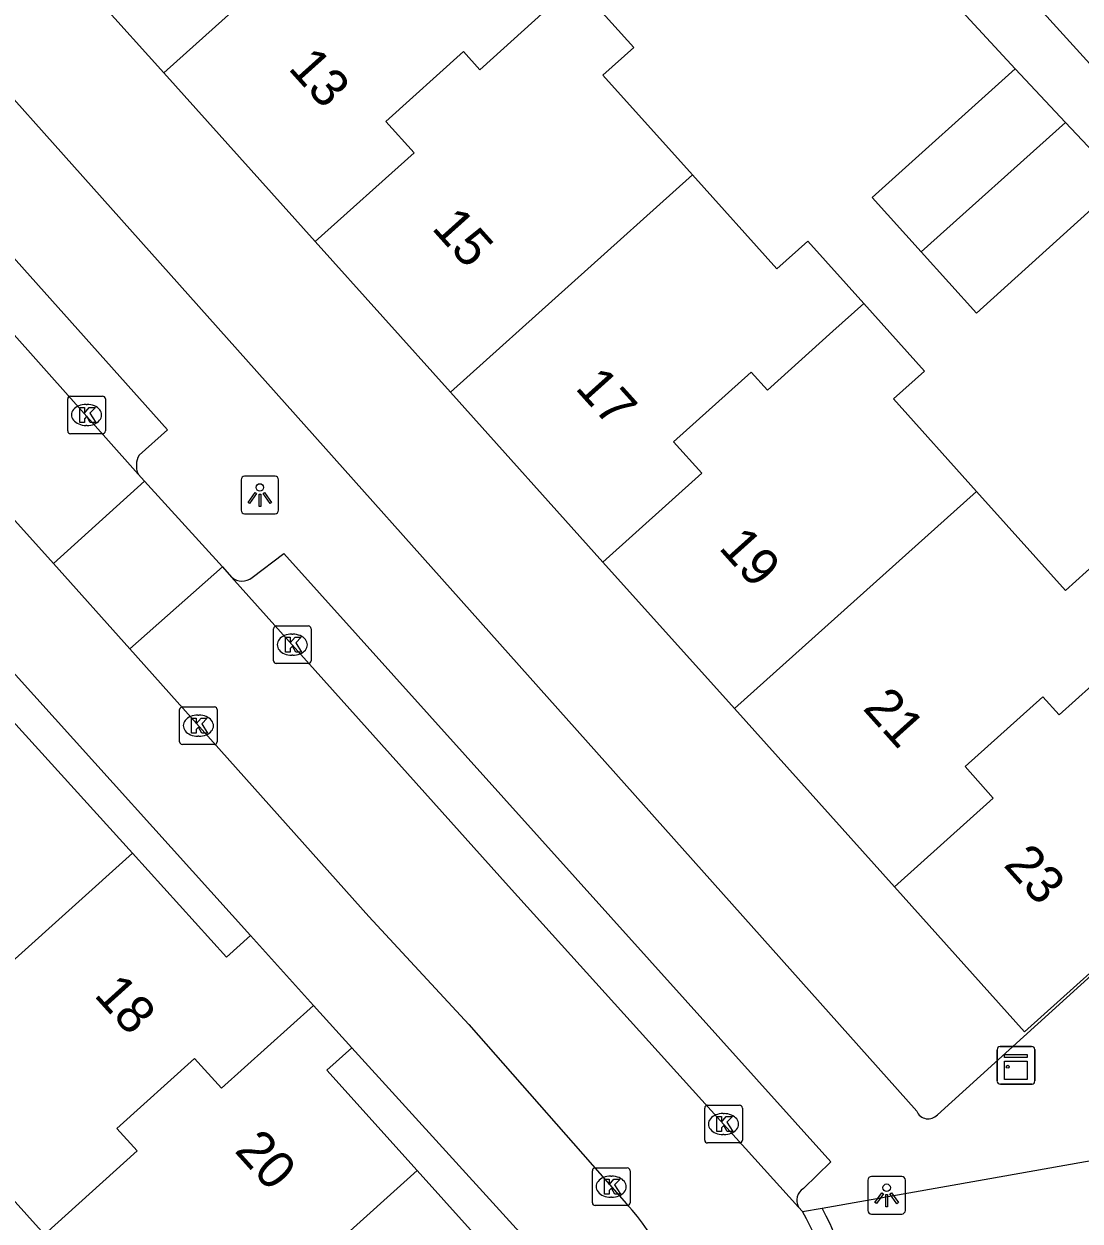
# Model space of a CAD drawing. Extents: x 162347 to 162868, y 381221 to 381813.
# Drawn here: x 162658.91 to 162687, y 381443.7 to 381475.54 of the extents above; entities that cross this region are included whole.
import ezdxf

# ---------------------------------------------------------------- set-up
doc = ezdxf.new("R2010")
doc.units = 0
for name, color, linetype in [('IMGEO_Kast', 7, 'Continuous'), ('IMGEO_Kolk', 7, 'Continuous'), ('IMGEO_Lichtpunt', 7, 'Continuous'), ('IMGEO_Pand', 7, 'Continuous'), ('IMGEO_Pand_nummerreeks', 7, 'Continuous'), ('IMGEO_Rijbaan_lokaal_gesloten', 7, 'Continuous'), ('IMGEO_Rijbaan_lokaal_open', 7, 'Continuous'), ('IMGEO_Voetpad_open', 7, 'Continuous')]:
    doc.layers.add(name, color=color, linetype=linetype)

msp = doc.modelspace()

# ---------------------------------------------------------------- linework, layer by layer
at = {"layer": 'IMGEO_Kast'}
for p, q in [((162684.796, 381447.418), (162684.796, 381448.259)), ((162684.796, 381448.259), (162684.796, 381447.418)), ((162684.871, 381448.343), (162685.712, 381448.343)), ((162685.712, 381448.343), (162684.871, 381448.343)), ((162685.796, 381448.268), (162685.796, 381447.427)), ((162685.796, 381447.427), (162685.796, 381448.268)), ((162685.721, 381447.343), (162684.88, 381447.343)), ((162684.88, 381447.343), (162685.721, 381447.343))]:
    msp.add_line(p, q, dxfattribs=at)
for points in [[(162684.991, 381448.133), (162685.591, 381448.133), (162685.591, 381448.048), (162684.991, 381448.048), (162684.991, 381448.133)], [(162684.991, 381447.958), (162685.591, 381447.958), (162685.591, 381447.469), (162684.991, 381447.469), (162684.991, 381447.958)]]:
    msp.add_lwpolyline(points, dxfattribs=at)
msp.add_circle((162685.075, 381447.807), 0.0377, dxfattribs=at)
for centre, start, end in [((162684.874, 381448.265), 92.4484, 184.2845), ((162684.874, 381448.265), 92.4484, 184.2845), ((162685.718, 381448.265), 2.4484, 94.2845), ((162685.718, 381448.265), 2.4484, 94.2845), ((162684.874, 381447.421), 182.4484, 274.2845), ((162684.874, 381447.421), 182.4484, 274.2845), ((162685.718, 381447.421), 272.4484, 4.2845), ((162685.718, 381447.421), 272.4484, 4.2845)]:
    msp.add_arc(centre, 0.0779, start, end, dxfattribs=at)
at = {"layer": 'IMGEO_Kolk'}
for p, q in [((162660.078, 381464.713), (162660.078, 381465.565)), ((162660.153, 381465.639), (162661.005, 381465.639)), ((162660.566, 381465.419), (162660.591, 381465.419)), ((162661.079, 381465.565), (162661.079, 381464.713)), ((162660.589, 381464.859), (162660.564, 381464.859)), ((162661.005, 381464.639), (162660.153, 381464.639)), ((162665.55, 381458.602), (162665.55, 381459.454)), ((162665.625, 381459.528), (162666.477, 381459.528)), ((162666.038, 381459.308), (162666.063, 381459.308)), ((162666.551, 381459.454), (162666.551, 381458.602)), ((162666.061, 381458.748), (162666.036, 381458.748)), ((162666.477, 381458.528), (162665.625, 381458.528)), ((162663.127, 381457.376), (162663.979, 381457.376)), ((162663.052, 381456.45), (162663.052, 381457.302)), ((162663.54, 381457.156), (162663.565, 381457.156)), ((162664.053, 381457.302), (162664.053, 381456.45)), ((162663.563, 381456.596), (162663.538, 381456.596)), ((162663.979, 381456.376), (162663.127, 381456.376)), ((162677.018, 381445.855), (162677.018, 381446.707)), ((162677.093, 381446.781), (162677.945, 381446.781)), ((162677.506, 381446.561), (162677.531, 381446.561)), ((162678.019, 381446.707), (162678.019, 381445.855)), ((162677.529, 381446.001), (162677.504, 381446.001)), ((162677.945, 381445.781), (162677.093, 381445.781)), ((162674.031, 381444.19), (162674.031, 381445.042)), ((162674.106, 381445.116), (162674.958, 381445.116)), ((162675.032, 381445.042), (162675.032, 381444.19)), ((162674.519, 381444.896), (162674.544, 381444.896)), ((162674.542, 381444.336), (162674.517, 381444.336)), ((162674.958, 381444.116), (162674.106, 381444.116))]:
    msp.add_line(p, q, dxfattribs=at)
for points in [[(162660.078, 381464.713), (162660.078, 381465.565)], [(162660.153, 381465.639), (162661.005, 381465.639)], [(162660.399, 381465.339), (162660.522, 381465.339), (162660.522, 381465.188), (162660.652, 381465.339), (162660.816, 381465.339), (162660.67, 381465.188), (162660.823, 381464.939), (162660.671, 381464.939), (162660.586, 381465.103), (162660.522, 381465.036), (162660.522, 381464.939), (162660.399, 381464.939), (162660.399, 381465.339)], [(162661.079, 381465.565), (162661.079, 381464.713)], [(162661.005, 381464.639), (162660.153, 381464.639)], [(162665.55, 381458.602), (162665.55, 381459.454)], [(162665.625, 381459.528), (162666.477, 381459.528)], [(162666.551, 381459.454), (162666.551, 381458.602)], [(162665.871, 381459.228), (162665.994, 381459.228), (162665.994, 381459.077), (162666.124, 381459.228), (162666.288, 381459.228), (162666.142, 381459.077), (162666.295, 381458.828), (162666.143, 381458.828), (162666.058, 381458.992), (162665.994, 381458.925), (162665.994, 381458.828), (162665.871, 381458.828), (162665.871, 381459.228)], [(162666.477, 381458.528), (162665.625, 381458.528)], [(162663.127, 381457.376), (162663.979, 381457.376)], [(162663.052, 381456.45), (162663.052, 381457.302)], [(162663.373, 381457.076), (162663.496, 381457.076), (162663.496, 381456.925), (162663.626, 381457.076), (162663.79, 381457.076), (162663.644, 381456.925), (162663.797, 381456.676), (162663.645, 381456.676), (162663.56, 381456.84), (162663.496, 381456.773), (162663.496, 381456.676), (162663.373, 381456.676), (162663.373, 381457.076)], [(162664.053, 381457.302), (162664.053, 381456.45)], [(162663.979, 381456.376), (162663.127, 381456.376)], [(162677.018, 381445.855), (162677.018, 381446.707)], [(162677.093, 381446.781), (162677.945, 381446.781)], [(162678.019, 381446.707), (162678.019, 381445.855)], [(162677.339, 381446.481), (162677.462, 381446.481), (162677.462, 381446.33), (162677.592, 381446.481), (162677.756, 381446.481), (162677.61, 381446.33), (162677.763, 381446.081), (162677.611, 381446.081), (162677.526, 381446.245), (162677.462, 381446.178), (162677.462, 381446.081), (162677.339, 381446.081), (162677.339, 381446.481)], [(162677.945, 381445.781), (162677.093, 381445.781)], [(162674.031, 381444.19), (162674.031, 381445.042)], [(162674.106, 381445.116), (162674.958, 381445.116)], [(162675.032, 381445.042), (162675.032, 381444.19)], [(162674.352, 381444.816), (162674.475, 381444.816), (162674.475, 381444.665), (162674.605, 381444.816), (162674.769, 381444.816), (162674.623, 381444.665), (162674.776, 381444.416), (162674.624, 381444.416), (162674.539, 381444.58), (162674.475, 381444.513), (162674.475, 381444.416), (162674.352, 381444.416), (162674.352, 381444.816)], [(162674.958, 381444.116), (162674.106, 381444.116)]]:
    msp.add_lwpolyline(points, dxfattribs=at)
for centre, start, end in [((162660.155, 381465.563), 91.552, 178.448), ((162660.155, 381465.563), 91.552, 178.448), ((162661.003, 381465.563), 1.552, 88.448), ((162661.003, 381465.563), 1.552, 88.448), ((162660.155, 381464.715), 181.552, 268.448), ((162660.155, 381464.715), 181.552, 268.448), ((162661.003, 381464.715), 271.552, 358.448), ((162661.003, 381464.715), 271.552, 358.448), ((162665.627, 381459.452), 91.552, 178.448), ((162665.627, 381459.452), 91.552, 178.448), ((162666.475, 381459.452), 1.552, 88.448), ((162666.475, 381459.452), 1.552, 88.448), ((162665.627, 381458.604), 181.552, 268.448), ((162665.627, 381458.604), 181.552, 268.448), ((162666.475, 381458.604), 271.552, 358.448), ((162666.475, 381458.604), 271.552, 358.448), ((162663.129, 381457.3), 91.552, 178.448), ((162663.129, 381457.3), 91.552, 178.448), ((162663.977, 381457.3), 1.552, 88.448), ((162663.977, 381457.3), 1.552, 88.448), ((162663.129, 381456.452), 181.552, 268.448), ((162663.129, 381456.452), 181.552, 268.448), ((162663.977, 381456.452), 271.552, 358.448), ((162663.977, 381456.452), 271.552, 358.448), ((162677.095, 381446.705), 91.552, 178.448), ((162677.095, 381446.705), 91.552, 178.448), ((162677.943, 381446.705), 1.552, 88.448), ((162677.943, 381446.705), 1.552, 88.448), ((162677.095, 381445.857), 181.552, 268.448), ((162677.095, 381445.857), 181.552, 268.448), ((162677.943, 381445.857), 271.552, 358.448), ((162677.943, 381445.857), 271.552, 358.448), ((162674.108, 381445.04), 91.552, 178.448), ((162674.108, 381445.04), 91.552, 178.448), ((162674.956, 381445.04), 1.552, 88.448), ((162674.956, 381445.04), 1.552, 88.448), ((162674.108, 381444.192), 181.552, 268.448), ((162674.108, 381444.192), 181.552, 268.448), ((162674.956, 381444.192), 271.552, 358.448), ((162674.956, 381444.192), 271.552, 358.448)]:
    msp.add_arc(centre, 0.0765, start, end, dxfattribs=at)
for centre, major_axis, ratio, start_param, end_param in [((162660.565, 381465.139), (-0.387, 0.002), 0.722429, 4.712389, 7.853982), ((162660.59, 381465.139), (-0.39, 0.002), 0.717154, 1.570796, 4.712389), ((162666.037, 381459.028), (-0.387, 0.002), 0.722429, 4.712389, 7.853982), ((162666.062, 381459.028), (-0.39, 0.002), 0.717154, 1.570796, 4.712389), ((162663.539, 381456.876), (-0.387, 0.002), 0.722429, 4.712389, 7.853982), ((162663.564, 381456.876), (-0.39, 0.002), 0.717154, 1.570796, 4.712389), ((162677.505, 381446.281), (-0.387, 0.002), 0.722429, 4.712389, 7.853982), ((162677.53, 381446.281), (-0.39, 0.002), 0.717154, 1.570796, 4.712389), ((162674.518, 381444.616), (-0.387, 0.002), 0.722429, 4.712389, 7.853982), ((162674.543, 381444.616), (-0.39, 0.002), 0.717154, 1.570796, 4.712389)]:
    msp.add_ellipse(centre, major_axis=major_axis, ratio=ratio, start_param=start_param, end_param=end_param, dxfattribs=at)
at = {"layer": 'IMGEO_Lichtpunt'}
for p, q in [((162665.591, 381463.508), (162664.783, 381463.508)), ((162665.591, 381463.508), (162664.783, 381463.508)), ((162664.689, 381463.413), (162664.689, 381462.606)), ((162664.689, 381463.413), (162664.689, 381462.606)), ((162665.685, 381462.606), (162665.685, 381463.413)), ((162665.685, 381462.606), (162665.685, 381463.413)), ((162664.783, 381462.512), (162665.591, 381462.512)), ((162664.783, 381462.512), (162665.591, 381462.512)), ((162681.357, 381444.791), (162681.357, 381443.984)), ((162681.357, 381444.791), (162681.357, 381443.984)), ((162682.259, 381444.886), (162681.451, 381444.886)), ((162682.259, 381444.886), (162681.451, 381444.886)), ((162682.353, 381443.984), (162682.353, 381444.791)), ((162682.353, 381443.984), (162682.353, 381444.791)), ((162681.451, 381443.89), (162682.259, 381443.89)), ((162681.451, 381443.89), (162682.259, 381443.89))]:
    msp.add_line(p, q, dxfattribs=at)
for points in [[(162665.063, 381463.077), (162665.102, 381463.049), (162664.914, 381462.787), (162664.876, 381462.814), (162665.063, 381463.077)], [(162665.165, 381463.029), (162665.212, 381463.029), (162665.212, 381462.707), (162665.165, 381462.707), (162665.165, 381463.029)], [(162665.275, 381463.049), (162665.313, 381463.076), (162665.5, 381462.814), (162665.461, 381462.786), (162665.275, 381463.049)], [(162681.731, 381444.455), (162681.77, 381444.427), (162681.582, 381444.165), (162681.544, 381444.192), (162681.731, 381444.455)], [(162681.833, 381444.407), (162681.88, 381444.407), (162681.88, 381444.085), (162681.833, 381444.085), (162681.833, 381444.407)], [(162681.943, 381444.427), (162681.981, 381444.454), (162682.168, 381444.192), (162682.129, 381444.164), (162681.943, 381444.427)]]:
    msp.add_lwpolyline(points, dxfattribs=at)
for centre in [(162665.188, 381463.211), (162681.856, 381444.589)]:
    msp.add_circle(centre, 0.0994, dxfattribs=at)
for centre, start, end in [((162664.783, 381463.413), 90, 180), ((162664.783, 381463.413), 90, 180), ((162665.591, 381463.413), 0, 90), ((162665.591, 381463.413), 0, 90), ((162664.783, 381462.606), 180, 270), ((162664.783, 381462.606), 180, 270), ((162665.591, 381462.606), 270, 0), ((162665.591, 381462.606), 270, 360), ((162681.451, 381444.791), 90, 180), ((162681.451, 381444.791), 90, 180), ((162682.259, 381444.791), 0, 90), ((162682.259, 381444.791), 0, 90), ((162681.451, 381443.984), 180, 270), ((162681.451, 381443.984), 180, 270), ((162682.259, 381443.984), 270, 0), ((162682.259, 381443.984), 270, 360)]:
    msp.add_arc(centre, 0.0946, start, end, dxfattribs=at)
at = {"layer": 'IMGEO_Pand'}
for points in [[(162662.631, 381474.235), (162669.067, 381480.013)], [(162659.214, 381478.042), (162662.631, 381474.235)], [(162673.599, 381476.62), (162672.776, 381475.881), (162671.038, 381474.32), (162670.607, 381474.799), (162668.538, 381472.942), (162669.289, 381472.107), (162666.661, 381469.747)], [(162676.69, 381471.522), (162674.312, 381474.17), (162675.135, 381474.91), (162673.795, 381476.401)], [(162685.27, 381474.344), (162681.471, 381470.918), (162682.774, 381469.473)], [(162686.611, 381472.919), (162685.27, 381474.344)], [(162662.631, 381474.235), (162666.661, 381469.747)], [(162682.774, 381469.473), (162686.611, 381472.919)], [(162688.04, 381471.271), (162688.106, 381471.33), (162686.611, 381472.919)], [(162670.254, 381465.745), (162676.69, 381471.522)], [(162681.249, 381468.103), (162679.758, 381469.763), (162678.933, 381469.023), (162676.69, 381471.522)], [(162682.774, 381469.473), (162684.241, 381467.846), (162688.04, 381471.271)], [(162666.661, 381469.747), (162670.254, 381465.745)], [(162674.309, 381461.228), (162676.937, 381463.588), (162676.186, 381464.423), (162678.255, 381466.28), (162678.686, 381465.801), (162680.424, 381467.362), (162681.249, 381468.103)], [(162684.245, 381463.106), (162682.036, 381465.566), (162682.861, 381466.307), (162681.249, 381468.103)], [(162670.254, 381465.745), (162674.309, 381461.228)], [(162684.245, 381463.106), (162677.81, 381457.329)], [(162689.004, 381459.468), (162687.435, 381461.214), (162686.609, 381460.473), (162684.245, 381463.106)], [(162674.309, 381461.228), (162677.81, 381457.329)], [(162682.063, 381452.592), (162684.691, 381454.952), (162683.94, 381455.787), (162686.009, 381457.644), (162686.44, 381457.165), (162688.178, 381458.726), (162689.004, 381459.468)], [(162682.063, 381452.592), (162685.525, 381448.735), (162691.96, 381454.512), (162689.628, 381457.109), (162690.455, 381457.852), (162689.004, 381459.468)], [(162661.798, 381453.482), (162658.353, 381457.286)], [(162677.81, 381457.329), (162682.063, 381452.592)], [(162655.467, 381447.783), (162661.798, 381453.482)], [(162664.937, 381451.295), (162664.299, 381450.721), (162661.798, 381453.482)], [(162666.613, 381449.436), (162664.937, 381451.295)], [(162666.613, 381449.436), (162664.169, 381447.232), (162663.451, 381448.028), (162661.387, 381446.167), (162661.928, 381445.567), (162659.46, 381443.343)], [(162667.63, 381448.308), (162666.613, 381449.436)], [(162669.374, 381445.044), (162666.971, 381447.716), (162667.63, 381448.308)], [(162659.46, 381443.343), (162655.467, 381447.783)], [(162669.374, 381445.044), (162663.05, 381439.352)], [(162673.628, 381440.312), (162669.374, 381445.044)]]:
    msp.add_lwpolyline(points, dxfattribs=at)
at = {"layer": 'IMGEO_Rijbaan_lokaal_gesloten'}
for points in [[(162661.949, 381463.568), (162654.995, 381471.374), (162645.092, 381482.381), (162637.045, 381491.405), (162632.206, 381496.785)], [(162659.702, 381461.185), (162659.547, 381461.359), (162651.674, 381470.086), (162640.833, 381482.197), (162629.754, 381494.514), (162629.654, 381494.622)], [(162661.949, 381463.568), (162662.119, 381463.377)], [(162664.198, 381461.096), (162664.438, 381460.828)], [(162664.438, 381460.828), (162671.802, 381452.604), (162679.513, 381444.074)], [(162661.728, 381458.92), (162668.09, 381451.805), (162670.743, 381448.931), (162674.935, 381444.16)], [(162679.513, 381444.074), (162679.621, 381443.954)]]:
    msp.add_lwpolyline(points, dxfattribs=at)
for centre, radius, start, end in [((162671.688, 381440.996), 4.534, 316.9573, 44.2512), ((162673.708, 381440.586), 6.805, 332.2275, 29.665)]:
    msp.add_arc(centre, radius, start, end, dxfattribs=at)
at = {"layer": 'IMGEO_Rijbaan_lokaal_open'}
for points in [[(162662.119, 381463.377), (162659.702, 381461.185)], [(162662.119, 381463.377), (162664.198, 381461.096)], [(162659.702, 381461.185), (162661.728, 381458.92)], [(162664.198, 381461.096), (162661.728, 381458.92)], [(162680.145, 381444.041), (162684.45, 381444.808), (162690.488, 381445.883), (162695.256, 381450.903), (162693.341, 381452.886)]]:
    msp.add_lwpolyline(points, dxfattribs=at)
msp.add_arc((162673.723, 381440.587), 7.292, 331.1337, 28.2749, dxfattribs=at)
at = {"layer": 'IMGEO_Voetpad_open'}
for points in [[(162682.655, 381446.622), (162635.433, 381499.549), (162635.925, 381500), (162637.034, 381501.017)], [(162632.873, 381496.892), (162633.504, 381497.442), (162662.73, 381464.743), (162661.975, 381464.068)], [(162680.383, 381479.645), (162685.27, 381474.344)], [(162683.29, 381478.831), (162685.58, 381476.325), (162688.135, 381473.509)], [(162652.435, 381465.161), (162664.937, 381451.295)], [(162664.979, 381460.817), (162665.826, 381461.458), (162680.373, 381445.274), (162679.641, 381444.571)], [(162692.575, 381453.33), (162691.689, 381454.221), (162683.206, 381446.525)], [(162674.063, 381441.248), (162667.63, 381448.308)], [(162679.621, 381443.954), (162680.145, 381444.041)]]:
    msp.add_lwpolyline(points, dxfattribs=at)
for centre, radius, start, end in [((162662.468, 381463.792), 0.565, 150.7478, 203.2988), ((162664.715, 381461.124), 0.405, 226.956, 310.7144), ((162682.962, 381446.755), 0.335, 203.3449, 316.6866), ((162679.836, 381444.256), 0.371, 121.7408, 209.3744)]:
    msp.add_arc(centre, radius, start, end, dxfattribs=at)

# ---------------------------------------------------------------- texts
at = {"layer": 'IMGEO_Pand_nummerreeks'}
for s, rotation, p in [('13', 311.9174, (162665.918, 381474.346)), ('15', 311.9174, (162669.734, 381470.095)), ('17', 311.9174, (162673.55, 381465.844)), ('19', 311.9174, (162677.367, 381461.593)), ('21', 311.9174, (162681.198, 381457.325)), ('23', 311.9174, (162684.94, 381453.159)), ('18', 312.0558, (162660.755, 381449.7)), ('20', 312.0558, (162664.489, 381445.561))]:
    msp.add_text(s, height=1, rotation=rotation, dxfattribs=at).set_placement(p)

doc.saveas('drawing.dxf')
